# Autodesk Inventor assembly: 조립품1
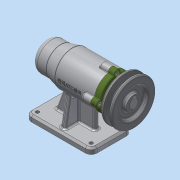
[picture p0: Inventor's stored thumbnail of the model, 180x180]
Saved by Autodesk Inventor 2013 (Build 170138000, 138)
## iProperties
Created: 2019-07
Part Number: 조립품1
Document SubType Name: Assembly
Designer: dgall
Author: dgall
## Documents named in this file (12)
- C:\Users\dgall\Desktop\490704v1040\조립품답안.iam
- C:\Users\dgall\Desktop\490704v1040\1번 본체.ipt
- C:\Users\dgall\Desktop\490704v1040\V벨트풀리.ipt
- C:\Users\dgall\Desktop\490704v1040\멈춤나사 M3.ipt
- C:\Users\dgall\Desktop\490704v1040\베어링 6004.ipt
- C:\Users\dgall\Desktop\490704v1040\베어링 51202.ipt
- C:\Users\dgall\Desktop\490704v1040\볼트 M4.ipt
- C:\Users\dgall\Desktop\490704v1040\어댑터슬리브.ipt
- C:\Users\dgall\Desktop\490704v1040\오일 실.ipt
- C:\Users\dgall\Desktop\490704v1040\축.ipt
- C:\Users\dgall\Desktop\490704v1040\커버.ipt
- C:\Users\dgall\Desktop\490704v1040\키 5 x 5 x 16.ipt
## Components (2 placed, 2 different names)
1. 1번 본체:1
2. V벨트풀리:1
